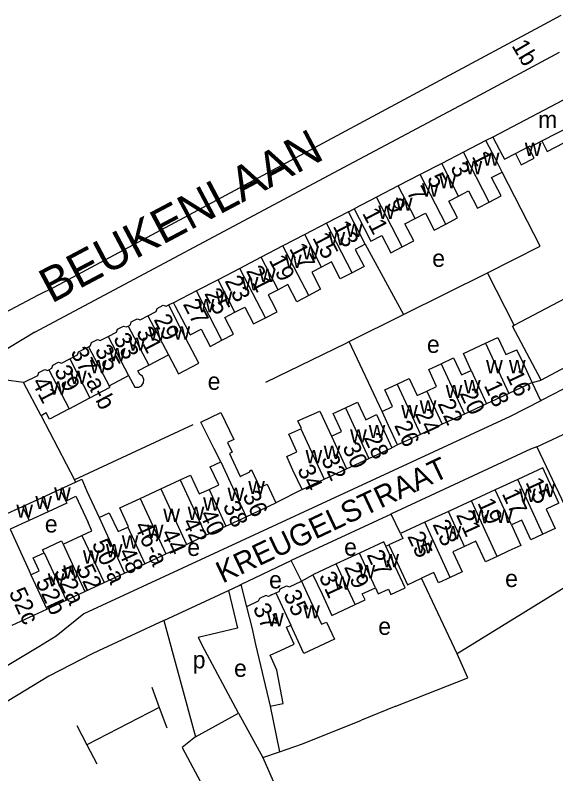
# Model space of a CAD drawing. Extents: x 159261 to 160849, y 382514 to 384534.
# Drawn here: x 159355.2 to 159480.6, y 384141.6 to 384317.4 of the extents above; entities that cross this region are included whole.
import ezdxf

# ---------------------------------------------------------------- set-up
doc = ezdxf.new("R2010")
doc.units = 0
for name, color, linetype in [('BLT_Basislijn', 7, 'Continuous'), ('BLT_Bebouwing', 7, 'Continuous'), ('BLT_Centroide', 7, 'Continuous'), ('BLT_Huisnummer', 7, 'Continuous'), ('BLT_Huisnummer_ tussenligend', 7, 'Continuous'), ('BLT_Huisnummer_reeks', 7, 'Continuous'), ('BLT_Huisnummer_zonder_bebouwing', 7, 'Continuous'), ('BLT_Onderverdeling_panden', 7, 'Continuous'), ('BLT_Straatnaam', 7, 'Continuous'), ('BLT_Straatnaam_hoofdweg', 7, 'Continuous')]:
    doc.layers.add(name, color=color, linetype=linetype)

msp = doc.modelspace()

# ---------------------------------------------------------------- linework, layer by layer
at = {"layer": 'BLT_Basislijn'}
for p, q in [((159426.72, 384287.84), (159453.73, 384302.33)), ((159430.19, 384281.46), (159461.86, 384298.34)), ((159364.29, 384254.33), (159426.72, 384287.84)), ((159465.96, 384289.16), (159464.35, 384288.35)), ((159359.78, 384243.93), (159430.19, 384281.46)), ((159432.53, 384271.82), (159433.82, 384272.5)), ((159436.41, 384264.35), (159445.27, 384248)), ((159445.27, 384248), (159464.7, 384257.7)), ((159470.91, 384245.57), (159464.7, 384257.7)), ((159391.97, 384250.74), (159390.83, 384250.26)), ((159432.66, 384241.75), (159445.27, 384248)), ((159440.3, 384225.58), (159432.66, 384241.75)), ((159475.11, 384232.27), (159477.18, 384232.85)), ((159477.12, 384228.05), (159475.11, 384232.27)), ((159476.19, 384217.39), (159487.84, 384222.84)), ((159443.91, 384217.8), (159442.58, 384217.13)), ((159476.19, 384217.39), (159486.05, 384196.44)), ((159369.02, 384209.73), (159369.26, 384209.22)), ((159421.74, 384207.47), (159415.66, 384204.38)), ((159442.4, 384201.8), (159419.25, 384191.01)), ((159444.6, 384197.29), (159442.4, 384201.8)), ((159441.18, 384194.37), (159441.9, 384194.67)), ((159407.57, 384185.47), (159419.25, 384191.01)), ((159421.63, 384186.22), (159419.25, 384191.01)), ((159421.63, 384186.22), (159424.27, 384187.73)), ((159457.7, 384169.43), (159449.41, 384186.91)), ((159407.57, 384185.47), (159408.9, 384180.33)), ((159389.7, 384177.14), (159374.57, 384170.08)), ((159407.02, 384155.65), (159398.58, 384171.39)), ((159460.15, 384163.87), (159457.7, 384169.43)), ((159443.47, 384157.29), (159460.15, 384163.87)), ((159386.9, 384161.72), (159388.65, 384157)), ((159388.65, 384157), (159371.86, 384148.36)), ((159388.65, 384157), (159390.41, 384152.28)), ((159414.35, 384157.25), (159416.5, 384146.7)), ((159443.47, 384157.29), (159435.56, 384154.06)), ((159369.57, 384152.8), (159371.86, 384148.36)), ((159397.08, 384150.2), (159393.92, 384147.72)), ((159371.86, 384148.36), (159374.14, 384143.91)), ((159393.92, 384147.72), (159400.69, 384135.11)), ((159412.64, 384145.43), (159416.5, 384146.7)), ((159412.64, 384145.43), (159423.8, 384120.14))]:
    msp.add_line(p, q, dxfattribs=at)
for points in [[(159477.92, 384315.29), (159481.84, 384317.39)], [(159453.73, 384302.33), (159477.92, 384315.29)], [(159461.86, 384298.34), (159481.42, 384308.79)], [(159464.7, 384257.7), (159476.93, 384263.85), (159468.15, 384281.02)], [(159319.44, 384226.57), (159322.96, 384229.27), (159326.54, 384231.9), (159330.16, 384234.46), (159333.82, 384236.96), (159337.53, 384239.4), (159341.29, 384241.76), (159345.08, 384244.06), (159348.92, 384246.29), (159352.8, 384248.45), (159356.71, 384250.54), (159360.66, 384252.56), (159364.29, 384254.33)], [(159518.09, 384249.2), (159477.37, 384228.18), (159477.12, 384228.05)], [(159359.78, 384243.93), (159350.54, 384238.37), (159343.47, 384232.95), (159339.93, 384229.41), (159335.45, 384224.46), (159331.44, 384221.15), (159322.01, 384213.61), (159317.11, 384209.28), (159311.39, 384202.56), (159306.6, 384195.11), (159302.72, 384188.52)], [(159413.38, 384232.36), (159431.94, 384241.39), (159432.66, 384241.75)], [(159357.21, 384232.3), (159352.65, 384232.93), (159346.52, 384227.03), (159340.62, 384220.89), (159337.29, 384217.89)], [(159477.12, 384228.05), (159470.01, 384224.44), (159371.13, 384178.67)], [(159361.24, 384224.59), (159369.02, 384209.73)], [(159396.45, 384222.5), (159369.02, 384209.73)], [(159476.19, 384217.39), (159474.67, 384216.81), (159442.67, 384201.93), (159442.4, 384201.8)], [(159489.54, 384189.02), (159457.7, 384169.43)], [(159389.7, 384177.14), (159404.69, 384184.12)], [(159404.69, 384184.12), (159406.81, 384175.34), (159397.67, 384173.16), (159398.58, 384171.39)], [(159404.69, 384184.12), (159407.15, 384185.27), (159407.57, 384185.47)], [(159371.13, 384178.67), (159364.73, 384173.51), (159360.71, 384171.07), (159340.01, 384158.65), (159336.85, 384156.95), (159335.05, 384156.5)], [(159389.7, 384177.14), (159397.08, 384150.2)], [(159374.57, 384170.08), (159373.09, 384169.39), (159363.04, 384164.24), (159338.68, 384149.51)], [(159397.08, 384150.2), (159407.02, 384155.65)], [(159407.02, 384155.65), (159412.64, 384145.43)], [(159416.5, 384146.7), (159421.85, 384148.53), (159435.56, 384154.06)]]:
    msp.add_lwpolyline(points, dxfattribs=at)
at = {"layer": 'BLT_Bebouwing'}
for p, q in [((159483.78, 384298.43), (159465.96, 384289.16)), ((159464.35, 384288.35), (159459.15, 384285.65)), ((159459.15, 384285.65), (159454.12, 384283.04)), ((159454.12, 384283.04), (159449.13, 384280.45)), ((159449.13, 384280.45), (159444.05, 384277.81)), ((159444.05, 384277.81), (159439.03, 384275.2)), ((159439.03, 384275.2), (159433.82, 384272.5)), ((159432.53, 384271.82), (159427.43, 384269.16)), ((159436.41, 384264.35), (159432.53, 384271.82)), ((159427.43, 384269.16), (159422.37, 384266.54)), ((159422.37, 384266.54), (159417.33, 384263.92)), ((159417.33, 384263.92), (159412.3, 384261.3)), ((159412.3, 384261.3), (159407.33, 384258.72)), ((159407.33, 384258.72), (159402.3, 384256.1)), ((159402.3, 384256.1), (159397.27, 384253.49)), ((159397.27, 384253.49), (159391.97, 384250.74)), ((159391.97, 384250.74), (159392.36, 384250)), ((159386.21, 384236.31), (159390.76, 384238.69)), ((159377.07, 384231.54), (159381.54, 384233.87)), ((159361.24, 384224.59), (159357.21, 384232.3)), ((159475.11, 384232.27), (159469.68, 384229.75)), ((159469.68, 384229.75), (159464.54, 384227.37)), ((159367.76, 384226.21), (159372.56, 384228.7)), ((159464.54, 384227.37), (159459.39, 384224.98)), ((159459.39, 384224.98), (159454.26, 384222.6)), ((159454.26, 384222.6), (159449.17, 384220.24)), ((159449.17, 384220.24), (159443.91, 384217.8)), ((159437.24, 384214.66), (159442.58, 384217.13)), ((159432.06, 384212.26), (159437.24, 384214.66)), ((159426.91, 384209.86), (159432.06, 384212.26)), ((159477.53, 384212.48), (159471.74, 384209.81)), ((159388.99, 384207.65), (159393.51, 384209.72)), ((159421.74, 384207.47), (159426.91, 384209.86)), ((159471.74, 384209.81), (159466.55, 384207.41)), ((159466.55, 384207.41), (159461.03, 384204.87)), ((159366.96, 384204.82), (159367.19, 384204.32)), ((159461.03, 384204.87), (159455.68, 384202.4)), ((159408.78, 384201.19), (159415.66, 384204.38)), ((159455.68, 384202.4), (159450.23, 384199.89)), ((159404.11, 384199.02), (159408.78, 384201.19)), ((159450.23, 384199.89), (159444.6, 384197.29)), ((159399.47, 384196.87), (159404.11, 384199.02)), ((159394.95, 384194.78), (159399.47, 384196.87)), ((159445.12, 384196.16), (159441.9, 384194.67)), ((159444.6, 384197.29), (159445.12, 384196.16)), ((159390.17, 384192.56), (159394.95, 384194.78)), ((159385.29, 384190.3), (159390.17, 384192.56)), ((159435.06, 384192.74), (159429.66, 384190.23)), ((159380.58, 384188.11), (159385.29, 384190.3)), ((159429.66, 384190.23), (159424.27, 384187.73)), ((159358.46, 384188.62), (159358.87, 384187.74)), ((159375.88, 384185.93), (159380.58, 384188.11)), ((159371.41, 384183.86), (159375.88, 384185.93)), ((159367.03, 384181.83), (159371.41, 384183.86)), ((159414.69, 384183.05), (159415.69, 384183.51)), ((159362.57, 384179.76), (159367.03, 384181.83)), ((159354.51, 384176.02), (159362.57, 384179.76))]:
    msp.add_line(p, q, dxfattribs=at)
for points in [[(159468.15, 384281.02), (159466.65, 384283.91), (159464.35, 384288.35)], [(159465.96, 384289.16), (159468.27, 384284.72), (159468.64, 384284), (159471.21, 384285.34)], [(159474.18, 384286.88), (159474.64, 384287.12), (159474.74, 384286.91), (159477.3, 384288.24)], [(159477.3, 384288.24), (159478.57, 384285.8), (159482.43, 384287.81), (159483.63, 384285.51)], [(159471.21, 384285.34), (159472.58, 384282.69), (159475.56, 384284.24), (159474.18, 384286.88)], [(159465.15, 384274.1), (159467.88, 384275.52), (159465.69, 384279.74), (159468.15, 384281.02)], [(159455.07, 384268.99), (159457.77, 384270.4), (159455.75, 384274.29), (159458.05, 384275.48)], [(159458.05, 384275.48), (159460.34, 384276.67), (159462.42, 384272.68), (159465.15, 384274.1)], [(159433.82, 384272.5), (159436.12, 384268.06), (159437.72, 384265), (159440.27, 384266.33), (159442.34, 384262.35), (159444.99, 384263.72)], [(159444.99, 384263.72), (159447.64, 384265.1), (159445.59, 384269.03), (159447.97, 384270.26)], [(159447.97, 384270.26), (159450.35, 384271.49), (159452.37, 384267.59), (159455.07, 384268.99)], [(159501.56, 384267.44), (159503.78, 384263.17), (159504.43, 384263.51), (159505.31, 384261.83), (159505.62, 384262), (159506.79, 384259.78), (159506.46, 384259.61), (159511.01, 384250.93), (159477.18, 384232.85)], [(159436.41, 384264.35), (159434.08, 384263.13), (159436.16, 384259.14), (159433.39, 384257.7)], [(159433.39, 384257.7), (159430.61, 384256.26), (159428.55, 384260.23), (159426.27, 384259.04)], [(159426.27, 384259.04), (159423.99, 384257.86), (159426.06, 384253.87), (159423.3, 384252.43)], [(159470.91, 384245.57), (159493.22, 384257.33)], [(159423.3, 384252.43), (159420.54, 384251), (159418.48, 384254.96), (159416.2, 384253.78)], [(159416.2, 384253.78), (159413.93, 384252.6), (159415.28, 384250)], [(159385.99, 384247.74), (159387.93, 384248.75), (159388.15, 384249.44), (159389.54, 384250.16), (159390.24, 384249.95), (159390.83, 384250.26)], [(159390.76, 384238.69), (159393.1, 384234.27), (159397.83, 384236.74), (159395.51, 384241.17), (159393.22, 384245.55), (159390.83, 384250.26)], [(159392.36, 384250), (159394.64, 384245.57), (159395.82, 384243.3), (159398.38, 384244.62), (159400.43, 384240.64), (159403.16, 384242.05)], [(159406.19, 384248.56), (159408.5, 384249.75), (159410.5, 384245.85), (159413.24, 384247.26)], [(159413.24, 384247.26), (159415.97, 384248.66), (159415.28, 384250)], [(159381.42, 384245.37), (159381.96, 384245.65), (159382.17, 384246.32), (159383.55, 384247.04), (159384.23, 384246.83), (159385.99, 384247.74)], [(159403.16, 384242.05), (159405.89, 384243.45), (159403.88, 384247.37), (159406.19, 384248.56)], [(159376.81, 384242.97), (159378.72, 384243.96), (159378.93, 384244.64), (159380.32, 384245.36), (159380.99, 384245.14), (159381.42, 384245.37)], [(159477.18, 384232.85), (159470.52, 384245.36), (159470.91, 384245.57)], [(159372.21, 384240.58), (159372.72, 384240.85), (159372.94, 384241.52), (159374.31, 384242.22), (159374.95, 384242.01), (159376.81, 384242.97)], [(159464.3, 384241.36), (159467.15, 384242.68), (159468.98, 384238.74), (159471.56, 384239.88)], [(159367.88, 384237.76), (159369.72, 384238.72), (159369.94, 384239.4), (159372.21, 384240.58)], [(159460.96, 384235.08), (159459.14, 384239), (159464.3, 384241.36)], [(159475.11, 384232.27), (159473, 384236.8), (159471.56, 384239.88)], [(159363.06, 384235.24), (159363.74, 384235.6), (159363.95, 384236.27), (159365.31, 384236.98), (159365.99, 384236.77), (159367.88, 384237.76)], [(159450.69, 384230.3), (159452.95, 384231.34), (159451.11, 384235.31), (159453.98, 384236.64)], [(159453.98, 384236.64), (159456.84, 384237.97), (159458.68, 384234.02), (159460.96, 384235.08)], [(159357.21, 384232.3), (159360.49, 384233.9), (159360.71, 384234.58), (159362.09, 384235.29), (159362.76, 384235.08), (159363.06, 384235.24)], [(159381.54, 384233.87), (159382.98, 384231.21), (159383.91, 384231.22), (159384.56, 384231.54), (159385.01, 384232.24), (159385.1, 384232.99), (159384.75, 384233.78), (159384.15, 384234.13), (159383.69, 384235), (159386.21, 384236.31)], [(159443.76, 384231.91), (159446.59, 384233.23), (159448.43, 384229.25), (159450.69, 384230.3)], [(159372.56, 384228.7), (159377.27, 384231.16), (159377.07, 384231.54)], [(159440.3, 384225.58), (159442.74, 384226.7), (159440.93, 384230.6), (159443.76, 384231.91)], [(159431.81, 384226.38), (159434.63, 384227.69), (159436.5, 384223.66), (159439.01, 384224.83), (159440.48, 384221.67), (159442.58, 384217.13)], [(159367.76, 384226.21), (159363.18, 384223.82), (159362.45, 384225.22), (159361.24, 384224.59)], [(159428.54, 384219.86), (159430.9, 384220.95), (159428.99, 384225.07), (159431.81, 384226.38)], [(159402.89, 384213.89), (159401.36, 384216.89), (159398.28, 384223.12), (159402.95, 384225.32), (159405.92, 384219.09), (159404.49, 384218.41), (159405.56, 384216.1), (159404.93, 384215.81), (159405.3, 384215.01), (159407.38, 384210.53), (159409.61, 384211.57), (159409.64, 384211.84), (159410.06, 384212.04), (159411.96, 384207.95), (159413.64, 384208.74), (159415.66, 384204.38)], [(159421.47, 384221.58), (159421.6, 384221.65), (159420.79, 384223.41), (159425.88, 384225.65), (159428.54, 384219.86)], [(159443.91, 384217.8), (159441.81, 384222.33), (159440.3, 384225.58)], [(159421.74, 384207.47), (159419.63, 384212), (159418.21, 384215.12), (159420.55, 384216.24), (159418.67, 384220.29), (159421.47, 384221.58)], [(159400.18, 384207.5), (159402.43, 384208.55), (159400.47, 384212.77), (159402.89, 384213.89)], [(159481.28, 384204.34), (159479.62, 384207.93), (159477.53, 384212.48)], [(159393.51, 384209.72), (159395.89, 384210.82), (159397.92, 384206.45), (159400.18, 384207.5)], [(159365.68, 384207.58), (159369.26, 384209.22)], [(159369.26, 384209.22), (159370.66, 384209.86), (159371.86, 384207.1), (159374.69, 384201)], [(159361.35, 384205.59), (159365.68, 384207.58)], [(159384.21, 384205.43), (159388.99, 384207.65)], [(159356.97, 384203.57), (159361.35, 384205.59)], [(159366.96, 384204.82), (159369.34, 384205.93), (159372.17, 384199.83)], [(159381.36, 384198.78), (159381.5, 384198.85), (159379.47, 384203.23), (159384.21, 384205.43)], [(159352.55, 384201.54), (159356.97, 384203.57)], [(159367.19, 384204.32), (159362.86, 384202.33)], [(159481.28, 384204.34), (159478.3, 384202.96), (159480.39, 384198.42), (159477.59, 384197.12)], [(159362.86, 384202.33), (159358.47, 384200.31)], [(159374.69, 384201), (159377.07, 384202.1), (159379.09, 384197.73), (159381.36, 384198.78)], [(159358.47, 384200.31), (159354.06, 384198.28)], [(159370.67, 384196.83), (159373.05, 384197.93), (159372.17, 384199.83)], [(159477.59, 384197.12), (159474.79, 384195.83), (159472.68, 384200.4), (159470.29, 384199.3)], [(159354.06, 384198.28), (159358.46, 384188.62)], [(159470.29, 384199.3), (159472.44, 384194.53), (159469.66, 384193.25), (159466.96, 384192)], [(159366.34, 384194.82), (159370.67, 384196.83)], [(159361.94, 384192.82), (159361.61, 384193.54), (159365.99, 384195.57), (159366.34, 384194.82)], [(159441.18, 384194.37), (159440.72, 384195.36), (159435.06, 384192.74)], [(159438.78, 384184.73), (159439.43, 384183.33), (159441.75, 384184.41), (159442.33, 384183.16), (159445.66, 384184.7), (159442.82, 384190.83), (159441.18, 384194.37)], [(159441.9, 384194.67), (159443.79, 384190.56), (159446.17, 384185.41), (159449.41, 384186.91)], [(159466.96, 384192), (159464.25, 384190.75), (159462.07, 384195.48), (159459.38, 384194.25)], [(159358.87, 384187.74), (159360.77, 384188.63), (159359.38, 384191.64), (159361.94, 384192.82)], [(159459.38, 384194.25), (159456.69, 384193.03), (159458.84, 384188.39), (159456.11, 384187.13)], [(159424.27, 384187.73), (159426.38, 384183.2), (159428.64, 384178.32), (159434.03, 384180.81)], [(159456.11, 384187.13), (159453.38, 384185.87), (159452.29, 384188.23), (159449.41, 384186.91)], [(159415.69, 384183.51), (159416.46, 384183.87), (159416.69, 384184.49), (159418.16, 384185.17), (159418.82, 384184.93), (159421.63, 384186.22)], [(159421.63, 384186.22), (159423.72, 384181.68), (159426.26, 384176.25), (159427.41, 384176.78), (159429.27, 384172.79)], [(159434.03, 384180.81), (159436.36, 384181.89), (159435.71, 384183.3), (159438.78, 384184.73)], [(159414.69, 384183.05), (159413.96, 384182.72), (159413.33, 384182.95), (159411.86, 384182.27), (159411.61, 384181.58), (159408.9, 384180.33)], [(159408.9, 384180.33), (159410.11, 384175.48), (159410.99, 384171.61), (159414.35, 384157.25)], [(159414.35, 384157.25), (159417.37, 384157.94), (159415.89, 384165.63), (159414.35, 384169.1), (159416.76, 384170.21), (159419.93, 384171.68), (159418.39, 384175.02), (159418.14, 384175.56), (159419.14, 384176.03)], [(159429.27, 384172.79), (159422.16, 384169.48), (159419.14, 384176.03)]]:
    msp.add_lwpolyline(points, dxfattribs=at)
at = {"layer": 'BLT_Onderverdeling_panden'}
for p, q in [((159477.3, 384288.24), (159488.78, 384294.21)), ((159471.21, 384285.34), (159474.18, 384286.88)), ((159465.15, 384274.1), (159459.15, 384285.65)), ((159458.05, 384275.48), (159454.12, 384283.04)), ((159455.07, 384268.99), (159449.13, 384280.45)), ((159447.97, 384270.26), (159444.05, 384277.81)), ((159444.99, 384263.72), (159439.03, 384275.2)), ((159433.39, 384257.7), (159427.43, 384269.16)), ((159426.27, 384259.04), (159422.37, 384266.54)), ((159423.3, 384252.43), (159417.33, 384263.92)), ((159416.2, 384253.78), (159412.3, 384261.3)), ((159413.24, 384247.26), (159407.33, 384258.72)), ((159406.19, 384248.56), (159402.3, 384256.1)), ((159403.16, 384242.05), (159397.27, 384253.49)), ((159385.99, 384247.74), (159390.76, 384238.69)), ((159381.42, 384245.37), (159386.21, 384236.31)), ((159376.81, 384242.97), (159381.54, 384233.87)), ((159372.21, 384240.58), (159377.07, 384231.54)), ((159464.3, 384241.36), (159469.68, 384229.75)), ((159367.88, 384237.76), (159372.56, 384228.7)), ((159453.98, 384236.64), (159459.39, 384224.98)), ((159363.06, 384235.24), (159367.76, 384226.21)), ((159460.96, 384235.08), (159464.54, 384227.37)), ((159443.76, 384231.91), (159449.17, 384220.24)), ((159450.69, 384230.3), (159454.26, 384222.6)), ((159431.81, 384226.38), (159437.24, 384214.66)), ((159421.47, 384221.58), (159426.91, 384209.86)), ((159428.54, 384219.86), (159432.06, 384212.26)), ((159402.89, 384213.89), (159408.78, 384201.19)), ((159393.51, 384209.72), (159399.47, 384196.87)), ((159477.59, 384197.12), (159471.74, 384209.81)), ((159365.68, 384207.58), (159366.96, 384204.82)), ((159388.99, 384207.65), (159394.95, 384194.78)), ((159400.18, 384207.5), (159404.11, 384199.02)), ((159470.29, 384199.3), (159466.55, 384207.41)), ((159361.35, 384205.59), (159362.86, 384202.33)), ((159384.21, 384205.43), (159390.17, 384192.56)), ((159466.96, 384192), (159461.03, 384204.87)), ((159356.97, 384203.57), (159358.47, 384200.31)), ((159459.38, 384194.25), (159455.68, 384202.4)), ((159374.69, 384201), (159380.58, 384188.11)), ((159456.11, 384187.13), (159450.23, 384199.89)), ((159381.36, 384198.78), (159385.29, 384190.3)), ((159370.67, 384196.83), (159375.88, 384185.93)), ((159366.34, 384194.82), (159371.41, 384183.86)), ((159361.94, 384192.82), (159367.03, 384181.83)), ((159438.78, 384184.73), (159435.06, 384192.74)), ((159434.03, 384180.81), (159429.66, 384190.23)), ((159358.87, 384187.74), (159362.57, 384179.76)), ((159415.69, 384183.51), (159419.14, 384176.03))]:
    msp.add_line(p, q, dxfattribs=at)

# ---------------------------------------------------------------- texts
at = {"layer": 'BLT_Centroide'}
for s, p in [('m', (159476.46, 384291.22)), ('w', (159473.38, 384284.78)), ('w', (159463.66, 384282.48)), ('w', (159459.64, 384280.52)), ('w', (159453.59, 384277.3)), ('w', (159449.56, 384275.36)), ('w', (159443.5, 384272.06)), ('w', (159439.41, 384270.17)), ('w', (159431.92, 384266.02)), ('w', (159427.88, 384264.08)), ('w', (159421.8, 384260.78)), ('w', (159417.8, 384258.83)), ('e', (159451.92, 384259.08)), ('w', (159411.77, 384255.56)), ('w', (159407.77, 384253.62)), ('w', (159401.73, 384250.33)), ('w', (159397.56, 384248.56)), ('w', (159391.94, 384242.23)), ('w', (159386.14, 384242)), ('w', (159381.52, 384239.62)), ('e', (159450.7, 384239.14)), ('w', (159376.97, 384237.2)), ('w', (159372.59, 384234.42)), ('w', (159464.41, 384234.39)), ('w', (159469.7, 384234.41)), ('w', (159367.94, 384231.92)), ('e', (159399.86, 384230.59)), ('w', (159363.25, 384229.48)), ('w', (159455.05, 384228.66)), ('w', (159459.27, 384229.77)), ('w', (159449.02, 384225.05)), ('w', (159444.73, 384224)), ('w', (159437.19, 384219.39)), ('w', (159432.89, 384218.34)), ('w', (159426.77, 384214.59)), ('w', (159422.56, 384213.55)), ('w', (159409.27, 384206.41)), ('w', (159476.52, 384205.73)), ('w', (159364.27, 384204.94)), ('w', (159404.47, 384204.83)), ('w', (159472.06, 384204.61)), ('w', (159359.91, 384202.94)), ('w', (159398.81, 384202.58)), ('w', (159355.51, 384200.94)), ('w', (159395.23, 384200.44)), ('w', (159389.58, 384199.94)), ('w', (159461.31, 384199.67)), ('w', (159466.73, 384199.75)), ('e', (159362.12, 384197.52)), ('w', (159385.77, 384196.28)), ('w', (159454.81, 384195.98)), ('w', (159379.95, 384193.8)), ('w', (159376.27, 384191.77)), ('e', (159395.14, 384192.09)), ('e', (159431.5, 384192.16)), ('w', (159448.2, 384192.66)), ('w', (159370.95, 384190.31)), ('w', (159440.36, 384189.47)), ('w', (159366.38, 384186.84)), ('w', (159434.83, 384186.91)), ('w', (159362.8, 384185.02)), ('e', (159414.11, 384184.57)), ('w', (159429.16, 384184.28)), ('e', (159468.82, 384184.89)), ('w', (159422.02, 384177.61)), ('w', (159413.66, 384175.81)), ('e', (159439.41, 384173.81)), ('p', (159396.4, 384166.05)), ('e', (159405.98, 384164.08))]:
    msp.add_text(s, height=4, dxfattribs=at).set_placement(p)
at = {"layer": 'BLT_Huisnummer'}
for s, rotation, p in [('1', 297.4296, (159461.01, 384284.69)), ('5', 297.4309, (159450.62, 384279.58)), ('13', 297.4634, (159428.8, 384268.52)), ('17', 297.4634, (159418.7, 384263.33)), ('21', 297.2546, (159408.68, 384258.15)), ('29', 297.5532, (159387.27, 384246.88)), ('33', 297.5746, (159377.88, 384242.49)), ('37-a-b', 297.5746, (159367.98, 384239.3)), ('16', 294.8914, (159468.96, 384234.01)), ('41', 297.5757, (159359.01, 384232.35)), ('20', 294.884, (159458.21, 384229.79)), ('24', 294.8831, (159447.79, 384225.1)), ('28', 294.8888, (159435.98, 384219.5)), ('34', 294.884, (159420.56, 384212.16)), ('15', 294.7487, (159473.49, 384209.17)), ('36', 294.8835, (159407.88, 384206.11)), ('19', 294.4429, (159462.33, 384204.42)), ('40', 294.8866, (159397.91, 384201.75)), ('25', 294.756, (159446.08, 384196.68)), ('44', 294.8881, (159388.94, 384197.34)), ('48', 294.8836, (159379.08, 384192.95)), ('27', 294.868, (159436.65, 384192.4)), ('52a', 294.8836, (159364.18, 384188.49)), ('52', 294.8836, (159369.43, 384189.05)), ('52b', 294.8836, (159359.9, 384186.13)), ('31', 294.8796, (159425.55, 384187.36)), ('52c', 294.8836, (159353.71, 384183.64)), ('35', 294.8626, (159417.32, 384183.15)), ('37', 294.7607, (159410.27, 384180.05))]:
    msp.add_text(s, height=4, rotation=rotation, dxfattribs=at).set_placement(p)
at = {"layer": 'BLT_Huisnummer_ tussenligend'}
for s, rotation, p in [('3', 297.4309, (159456.02, 384282.06)), ('7', 297.4309, (159445.88, 384276.43)), ('9', 297.4309, (159441.16, 384273.72)), ('11', 297.4309, (159435.61, 384271.51)), ('15', 297.4634, (159424.07, 384265.82)), ('19', 297.4634, (159413.98, 384260.62)), ('23', 297.2546, (159403.74, 384255.84)), ('25', 297.2546, (159399.01, 384252.91)), ('27', 297.2546, (159394.05, 384250.45)), ('31', 297.5532, (159383.2, 384243.99)), ('35', 297.5746, (159373.6, 384239.79)), ('39', 297.5746, (159364.2, 384235.03)), ('18', 294.8914, (159463.84, 384231.62)), ('22', 294.884, (159453.09, 384227.4)), ('26', 294.8831, (159443.03, 384222.35)), ('30', 294.8888, (159431.03, 384217.31)), ('32', 294.8888, (159426.09, 384214.55)), ('17', 294.7487, (159468, 384206.55)), ('38', 294.8835, (159403.3, 384203.72)), ('21', 294.4429, (159457.38, 384201.63)), ('42', 294.8866, (159393.89, 384199.91)), ('23', 294.4429, (159451.94, 384199.42)), ('29', 294.868, (159431.4, 384189.53))]:
    msp.add_text(s, height=4, rotation=rotation, dxfattribs=at).set_placement(p)
at = {"layer": 'BLT_Huisnummer_reeks'}
for s, rotation, p in [('46-a', 294.8881, (159382.75, 384199.07)), ('50-a', 294.885, (159372.93, 384194.9))]:
    msp.add_text(s, height=4, rotation=rotation, dxfattribs=at).set_placement(p)
at = {"layer": 'BLT_Huisnummer_zonder_bebouwing'}
msp.add_text('1b', height=4, rotation=300.3478, dxfattribs=at).set_placement((159470.23, 384310.34))
at = {"layer": 'BLT_Straatnaam'}
msp.add_text('KREUGELSTRAAT', height=4.9999, rotation=25.3572, dxfattribs=at).set_placement((159403.33, 384185.69))
at = {"layer": 'BLT_Straatnaam_hoofdweg'}
msp.add_text('BEUKENLAAN', height=8, rotation=27.9118, dxfattribs=at).set_placement((159363.66, 384250.5))

doc.saveas('drawing.dxf')
